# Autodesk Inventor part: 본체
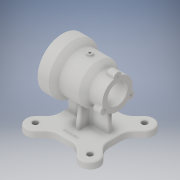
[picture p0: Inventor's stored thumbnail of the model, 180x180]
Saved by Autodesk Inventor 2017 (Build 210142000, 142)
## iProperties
Part Number: 본체
Material: 일반
Document SubType Name: Modeling
Designer: jhkim
Density: 1 g/cm^3
Appearance: 기본값
Author: jhkim
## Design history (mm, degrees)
sketch "스케치1"
  geometry: L1 (-45, -45)-(45, -45); L2 (45, -45)-(45, 45); L3 (45, 45)-(-45, 45); L4 (-45, 45)-(-45, -45); L5 (-45, -45)-(45, 45); L6 (45, -45)-(-45, 45); 1 further point
  constraints: 12 end point, 2 midpoint, 2 parallel, 1 horizontal, 1 perpendicular
  dimensions: "d0" = 90 distance of L3.end L2.end; "d1" = 90 distance of L2.end L1.end
extrude "돌출1" new body sketch "스케치1" distance "d2" = 12; taper "d3" = 0 deg
sketch "스케치2"
  geometry: L1 (49.497, 49.497)-(-49.497, -49.497); L2 (0, 0)-(78.808, 0); L3 (45, -45)-(-45, -45) reference; L4 (45, 45)-(45, -45) reference; L5 (-45, 45)-(45, 45) reference; L6 (-45, -45)-(-45, 45) reference; L7 (20.958, 45)-(37.477, 61.518); L8 (45, 20.958)-(61.518, 37.477); L9 (45, 45)-(45, -45) reference; L10 (45, 20.958)-(45, 45); L11 (45, 45)-(20.958, 45); L12 (-45, 45)-(45, 45) reference; L13 (45, 20.958)-(45, 45); L14 (-20.958, 45)-(-37.477, 61.518); L15 (-45, 20.958)-(-61.518, 37.477); L16 (-45, 45)-(-45, 20.958); L17 (-20.958, 45)-(-45, 45); L18 (-45, -20.958)-(-61.518, -37.477); L19 (-20.958, -45)-(-37.477, -61.518); L20 (-45, -45)-(-20.958, -45); L21 (-45, -20.958)-(-45, -45); L22 (20.958, -45)-(37.477, -61.518); L23 (45, -20.958)-(61.518, -37.477); L24 (45, -45)-(45, -20.958); L25 (20.958, -45)-(45, -45); A1 r 70 centre (0, 0) between (49.497, 49.497) and (-49.497, -49.497); A2 r 17 centre (49.497, 49.497) between (33.103, 45) and (45, 33.103); A3 r 17 centre (49.497, 49.497) between (61.518, 37.477) and (37.477, 61.518); A4 r 17 centre (-49.497, 49.497) between (-37.477, 61.518) and (-61.518, 37.477); A5 r 17 centre (-49.497, -49.497) between (-61.518, -37.477) and (-37.477, -61.518); A6 r 17 centre (49.497, -49.497) between (37.477, -61.518) and (61.518, -37.477); 1 further point
  constraints: 38 end point, 12 point on circle, 6 centre point, 3 point on line, 2 coincident, 2 collinear, 2 symmetric about line, 1 horizontal, 1 midpoint, 1 perpendicular, 1 tangent, 45 other
  dimensions: "d4" = 140 diameter of A1; "d5" = 45 deg angle of L2 L1; "d7" = 45 deg angle of L7 L2; "d10" = 360 deg dimension on point (0, 0) A2.centre (derived)
extrude "돌출2" join sketch "스케치2" distance "d12" = 12; taper "d13" = 0 deg
fillet "모깎기1" dims "d14" = 25
sketch "스케치3"
  geometry: L1 (37, -4)-(37, 4); L2 (-37, 4)-(-37, -4); L3 (-37, -4)-(37, 4); L4 (37, -4)-(-37, 4); L5 (-4, -25)-(4, -25); L6 (4, 25)-(-4, 25); L7 (-4, -25)-(4, 25); L8 (4, -25)-(-4, 25); L9 (37, 4)-(4, 4); L10 (-4, 4)-(-37, 4); L11 (-4, 25)-(-4, 4); L12 (4, -25)-(4, -4); L13 (4, 4)-(4, 25); L14 (-37, -4)-(-4, -4); L15 (4, -4)-(37, -4); L16 (-4, -4)-(-4, -25); 1 further point
  constraints: 32 end point, 10 parallel, 4 midpoint, 4 perpendicular, 3 horizontal
  dimensions: "d15" = 74 distance of L2.start L1.end; "d16" = 8 distance of L1.end L1.start; "d17" = 8 distance of L6.end L6.start; "d18" = 50 distance of L6.start L5.end; "d19" = 4 distance from line of L13 point (0, 0); "d20" = 4 distance from line of L10 point (0, 0); "d21" = 25 distance from line of L6 point (0, 0); "d22" = 37 distance from line of L2 point (0, 0)
node "작업 평면1"
sketch "스케치4"
  geometry: L1 (-50, 0)-(-50, 45); L2 (-50, 45)-(-30, 45); L3 (-30, 45)-(-19, 36); L4 (-19, 36)-(15, 36); L5 (15, 36)-(27, 27.5); L6 (27, 27.5)-(50, 27.5); L7 (50, 27.5)-(50, 0); L8 (-50, 0)-(50, 0); 1 further point
  constraints: 16 end point, 2 parallel, 2 perpendicular, 1 midpoint, 1 vertical
  dimensions: "d24" = 50 distance from line of L1 point (0, 0); "d25" = 90 diameter of L2 L8; "d26" = 20 distance from line of L2.end L1; "d27" = 65 distance from line of L4.end L1; "d28" = 23 distance from line of L7 L5.end; "d29" = 100 distance between parallel lines of L7 L1; "d30" = 55 diameter of L6 L8; "d31" = 72 diameter of L4 L8; "d32" = 31 distance from line of L3.end L1
revolve "회전1" sketch "스케치4" stored, may be unused: angle "d33" = 90 deg
sketch "스케치5"
  geometry: 1 further point
sketch "스케치6"
  geometry: C1 r 45 at (0, 0) reference; C2 r 35 at (0, 0); 1 further point
  constraints: 1 centre point, 1 coincident
  dimensions: "d34" = 70 diameter of C2
extrude "돌출3" cut sketch "스케치6" distance "d35" = 23; taper "d36" = 0 deg
sketch "스케치7"
  geometry: C1 r 35 at (0, 0) reference; C2 r 23.5 at (0, 0); 1 further point
  constraints: 1 centre point, 1 coincident
  dimensions: "d37" = 47 diameter of C2
extrude "돌출4" cut sketch "스케치7" distance "d38" = 47; taper "d39" = 0 deg
sketch "스케치8"
  geometry: C1 r 23.5 at (0, 0) reference; C2 r 17.5 at (0, 0); 1 further point
  constraints: 1 centre point, 1 coincident
  dimensions: "d40" = 35 diameter of C2
extrude "돌출5" cut sketch "스케치8" stored distance "d41" = 47; taper "d42" = 0 deg
fillet "모깎기2" dims "d43" = 3
chamfer "모따기1" distance "d44" = 1; stored, may be unused: second distance "d45" = 2, angle "d46" = 45 deg
extrude "돌출6" join sketch "스케치3" stored distance "d47" = 47; taper "d48" = 0 deg
feature "면 기울기1" dims angle "d49" = 10 deg
feature "면 기울기2" dims angle "d50" = 10 deg
sketch "스케치9"
  geometry: C1 r 7 at (-27.5, 0); C2 r 7 at (13.75, -23.816); C3 r 7 at (13.75, 23.816); 2 further points
  constraints: 3 centre point, 2 horizontal alignment, 8 other
  dimensions: "d51" = 7 radius of C1; "d54" = 360 deg dimension on point (0, 0) C1.centre (derived)
extrude "돌출7" join sketch "스케치9" distance "d56" = 15; taper "d57" = 0 deg
sketch "스케치10"
  geometry: C1 r 18.5 at (27.5, 0) reference; A1 r 27.5 centre (27.5, 0) between (34.792, 26.516) and (0.891, 6.943) reference; A2 r 7 centre (0, 0) between (0.891, 6.943) and (0.891, -6.943) reference; A3 r 27.5 centre (27.5, 0) between (0.891, -6.943) and (34.792, -26.516) reference; A4 r 7 centre (41.25, -23.816) between (34.792, -26.516) and (46.817, -19.573) reference; A5 r 27.5 centre (27.5, 0) between (46.817, -19.573) and (46.817, 19.573) reference; A6 r 7 centre (41.25, 23.816) between (46.817, 19.573) and (34.792, 26.516) reference; 4 further points
  constraints: 3 coincident
hole "구멍1" sketch "스케치10" at (0, 0), (41.25, -23.816), (41.25, 23.816) diameter "d58" = 3.242; stored, may be unused: countersink angle "d62" = 90 deg, drill point angle "d64" = 118 deg; dims "d59" = 9, "d60" = 4, "d61" = 2, "d63" = 11
sketch "스케치11" dims "d65" = 80
  geometry: C1 r 45 at (0, 0) reference; C2 r 36 at (0, 0) reference; 8 further points
  constraints: 2 horizontal alignment, 1 coincident, 9 other
  dimensions: "d68" = 360 deg dimension on C1.centre point (40, 0) (derived)
hole "구멍2" sketch "스케치11" at (40, 0), (20, 34.641), (-20, 34.641), (-40, 0), (-20, -34.641), (20, -34.641) diameter "d70" = 3.242; stored, may be unused: countersink angle "d74" = 90 deg, drill point angle "d76" = 118 deg; dims "d71" = 9, "d72" = 4, "d73" = 2, "d75" = 11
node "작업 평면2"
sketch "스케치12"
  geometry: L1 (50, 45)-(50, -45) reference; C1 r 5 at (0, 0); 1 further point
  constraints: 1 centre point, 1 coincident
  dimensions: "d78" = 10 diameter of C1
extrude "돌출8" join sketch "스케치12" stored distance "d79" = 15; taper "d80" = 0 deg; dims "d4" = 140, "d5" = 45 deg, "d7" = 45 deg, "d10" = 360 deg (derived)
sketch "스케치13"
  geometry: 2 further points
  constraints: 1 coincident
hole "구멍3" sketch "스케치13" at (0, 0) diameter "d81" = 4.134; stored, may be unused: countersink angle "d85" = 90 deg, drill point angle "d87" = 118 deg; dims "d82" = 10, "d83" = 4, "d84" = 2, "d86" = 14.2
fillet "모깎기3" dims "d88" = 3
fillet "모깎기4" dims "d89" = 3
fillet "모깎기5" dims "d90" = 3
fillet "모깎기6" dims "d91" = 3
fillet "모깎기7" dims "d92" = 3
fillet "모깎기8" dims "d93" = 3
fillet "모깎기9" dims "d94" = 3
fillet "모깎기10" dims "d95" = 1
sketch "스케치14"
  geometry: L1 (-40, 1)-(-40, -1) reference; L2 (-7, 7)-(-34, 7) reference; L3 (-7, 21.425)-(-7, 7) reference; L4 (1, 27.517)-(-1, 27.517) reference; L5 (7, 7)-(7, 21.425) reference; L6 (34, 7)-(7, 7) reference; L7 (40, -1)-(40, 1) reference; L8 (7, -7)-(34, -7) reference; L9 (7, -21.425)-(7, -7) reference; L10 (-1, -27.517)-(1, -27.517) reference; L11 (-7, -7)-(-7, -21.425) reference; L12 (-34, -7)-(-7, -7) reference; L13 (39.598, -59.397)-(30.402, -50.201) reference; L14 (50.201, -30.402)-(59.397, -39.598) reference; L15 (42, 10.603)-(42, -10.603) reference; L16 (59.397, 39.598)-(50.201, 30.402) reference; L17 (30.402, 50.201)-(39.598, 59.397) reference; L18 (-10.603, 42)-(10.603, 42) reference; L19 (-39.598, 59.397)-(-30.402, 50.201) reference; L20 (-50.201, 30.402)-(-59.397, 39.598) reference; L21 (-42, -10.603)-(-42, 10.603) reference; L22 (-59.397, -39.598)-(-50.201, -30.402) reference; L23 (-30.402, -50.201)-(-39.598, -59.397) reference; L24 (10.603, -42)-(-10.603, -42) reference; A1 r 6 centre (-34, -1) between (-40, -1) and (-34, -7) reference; A2 r 6 centre (-34, 1) between (-34, 7) and (-40, 1) reference; A3 r 6 centre (34, 1) between (40, 1) and (34, 7) reference; A4 r 6 centre (34, -1) between (34, -7) and (40, -1) reference; A5 r 28 centre (10.603, -70) between (30.402, -50.201) and (10.603, -42) reference; A6 r 14 centre (49.497, -49.497) between (39.598, -59.397) and (59.397, -39.598) reference; A7 r 28 centre (70, -10.603) between (42, -10.603) and (50.201, -30.402) reference; A8 r 28 centre (70, 10.603) between (50.201, 30.402) and (42, 10.603) reference; A9 r 14 centre (49.497, 49.497) between (59.397, 39.598) and (39.598, 59.397) reference; A10 r 28 centre (10.603, 70) between (10.603, 42) and (30.402, 50.201) reference; A11 r 28 centre (-10.603, 70) between (-30.402, 50.201) and (-10.603, 42) reference; A12 r 14 centre (-49.497, 49.497) between (-39.598, 59.397) and (-59.397, 39.598) reference; A13 r 28 centre (-70, 10.603) between (-42, 10.603) and (-50.201, 30.402) reference; A14 r 28 centre (-70, -10.603) between (-50.201, -30.402) and (-42, -10.603) reference; A15 r 14 centre (-49.497, -49.497) between (-59.397, -39.598) and (-39.598, -59.397) reference; A16 r 28 centre (-10.603, -70) between (-10.603, -42) and (-30.402, -50.201) reference; 9 further points; 4 other entities
  constraints: 4 coincident, 4 other
hole "구멍4" sketch "스케치14" at (-49.497, 49.497), (-49.497, -49.497), (49.497, -49.497), (49.497, 49.497) diameter "d96" = 10; stored, may be unused: countersink angle "d100" = 90 deg, drill point angle "d102" = 0 deg; dims "d97" = 10, "d98" = 4, "d99" = 2, "d101" = 14.2
sketch "스케치15"
  geometry: 2 further points
  constraints: 1 vertical alignment, 1 other
  dimensions: "d103" = 35 distance of point (0, -35) point (0, 0)
feature "엠보싱1" sketch "스케치15" dims "d4" = 140, "d5" = 45 deg, "d7" = 45 deg, "d10" = 360 deg (derived), "d104" = 0.5, "d105" = 0
node "솔리드1"
node "투영된 루프1"
node "투영된 루프2"
node "투영된 루프3"
node "투영된 루프4"
node "투영된 루프5"
node "투영된 루프6"
node "투영된 루프7"
other parameters: "d6" = 34, "d23" = 82, "d77" = -122
